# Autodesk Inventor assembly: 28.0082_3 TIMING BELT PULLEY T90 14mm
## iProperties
Created: 2007-04
Part Number: 28.0082_3 TIMING BELT PULLEY T90 14mm
Document SubType Name: Assembly
Designer: Andy Moles
Author: Andy Moles
